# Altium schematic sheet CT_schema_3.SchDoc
size 199 x 169 mm
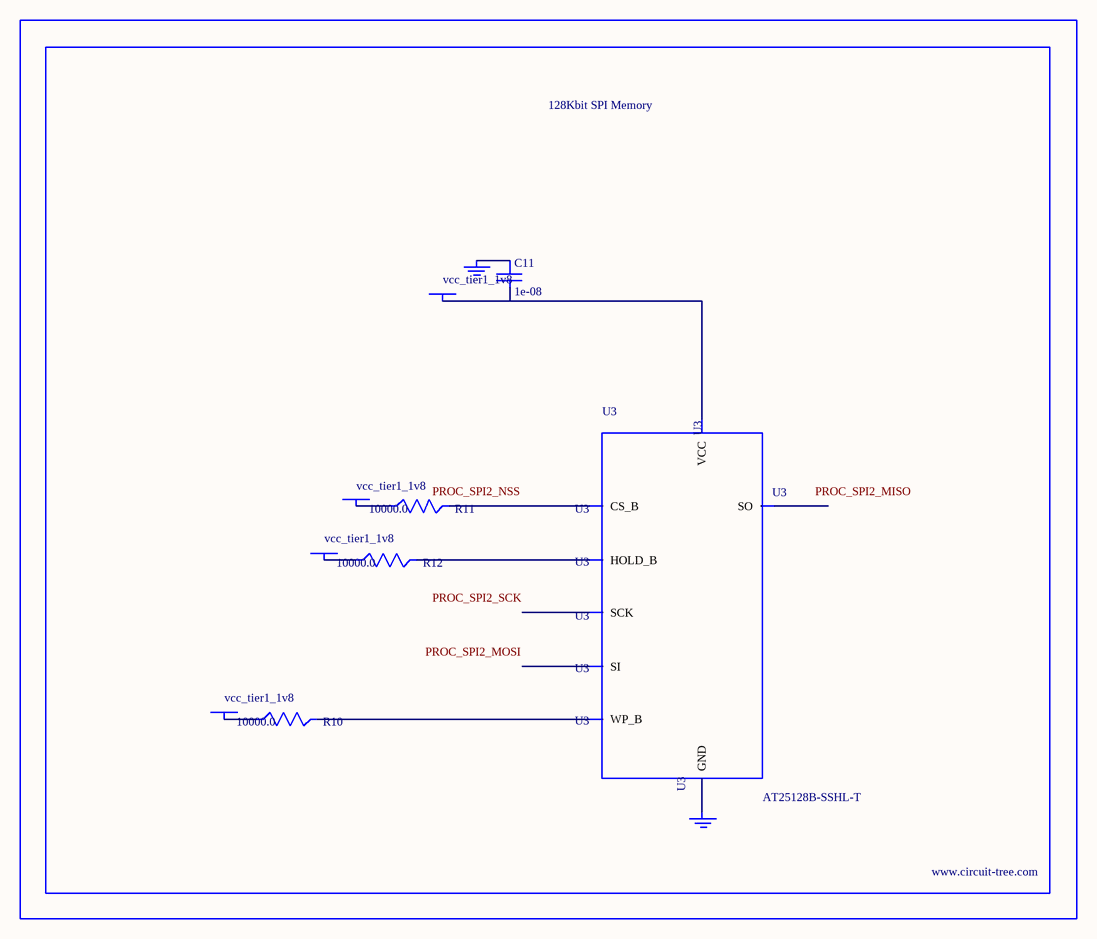
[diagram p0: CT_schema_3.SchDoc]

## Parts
BORDER2  (no value)
C11  1e-08  [C0402]
GND_INSTANCE_2_0  (no value)
GND_INSTANCE_2_1  (no value)
POWER_INSTANCE_2_0  vcc_tier1_1v8
POWER_INSTANCE_2_1  vcc_tier1_1v8
POWER_INSTANCE_2_2  vcc_tier1_1v8
POWER_INSTANCE_2_3  vcc_tier1_1v8
R10  10000.0  [R0603]
R11  10000.0  [R0603]
R12  10000.0  [R0603]
U3  AT25128B-SSHL-T  [SOIC-8]

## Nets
NetC11_1: C11.1 GND_INSTANCE_2_0.0(GND)
NetC11_2: C11.2 POWER_INSTANCE_2_3.0(PWR) U3.8(VCC)
NetGND_INSTANCE_2_1_0: GND_INSTANCE_2_1.0(GND) U3.4(GND)
NetPOWER_INSTANCE_2_0_0: POWER_INSTANCE_2_0.0(PWR) R11.1
NetPOWER_INSTANCE_2_1_0: POWER_INSTANCE_2_1.0(PWR) R10.1
NetPOWER_INSTANCE_2_2_0: POWER_INSTANCE_2_2.0(PWR) R12.1
NetR10_2: R10.2 U3.3(WP_B)
NetR11_2: R11.2 U3.1(CS_B)
NetR12_2: R12.2 U3.7(HOLD_B)

Not connected (* = marked no-connect by the designer): U3 2(SO) 5(SI) 6(SCK)

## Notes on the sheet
- Labels drawn without touching a wire or pin: PROC_SPI2_MISO, PROC_SPI2_MOSI, PROC_SPI2_NSS, PROC_SPI2_SCK

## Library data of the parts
BORDER2 = BORDER_PAGE2
C11 = C0402C103K3RAC
GND_INSTANCE_2_0 GND_INSTANCE_2_1 = GND
POWER_INSTANCE_2_0-POWER_INSTANCE_2_3 = PWR
R10-R12 = RC0603JR-0710KL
